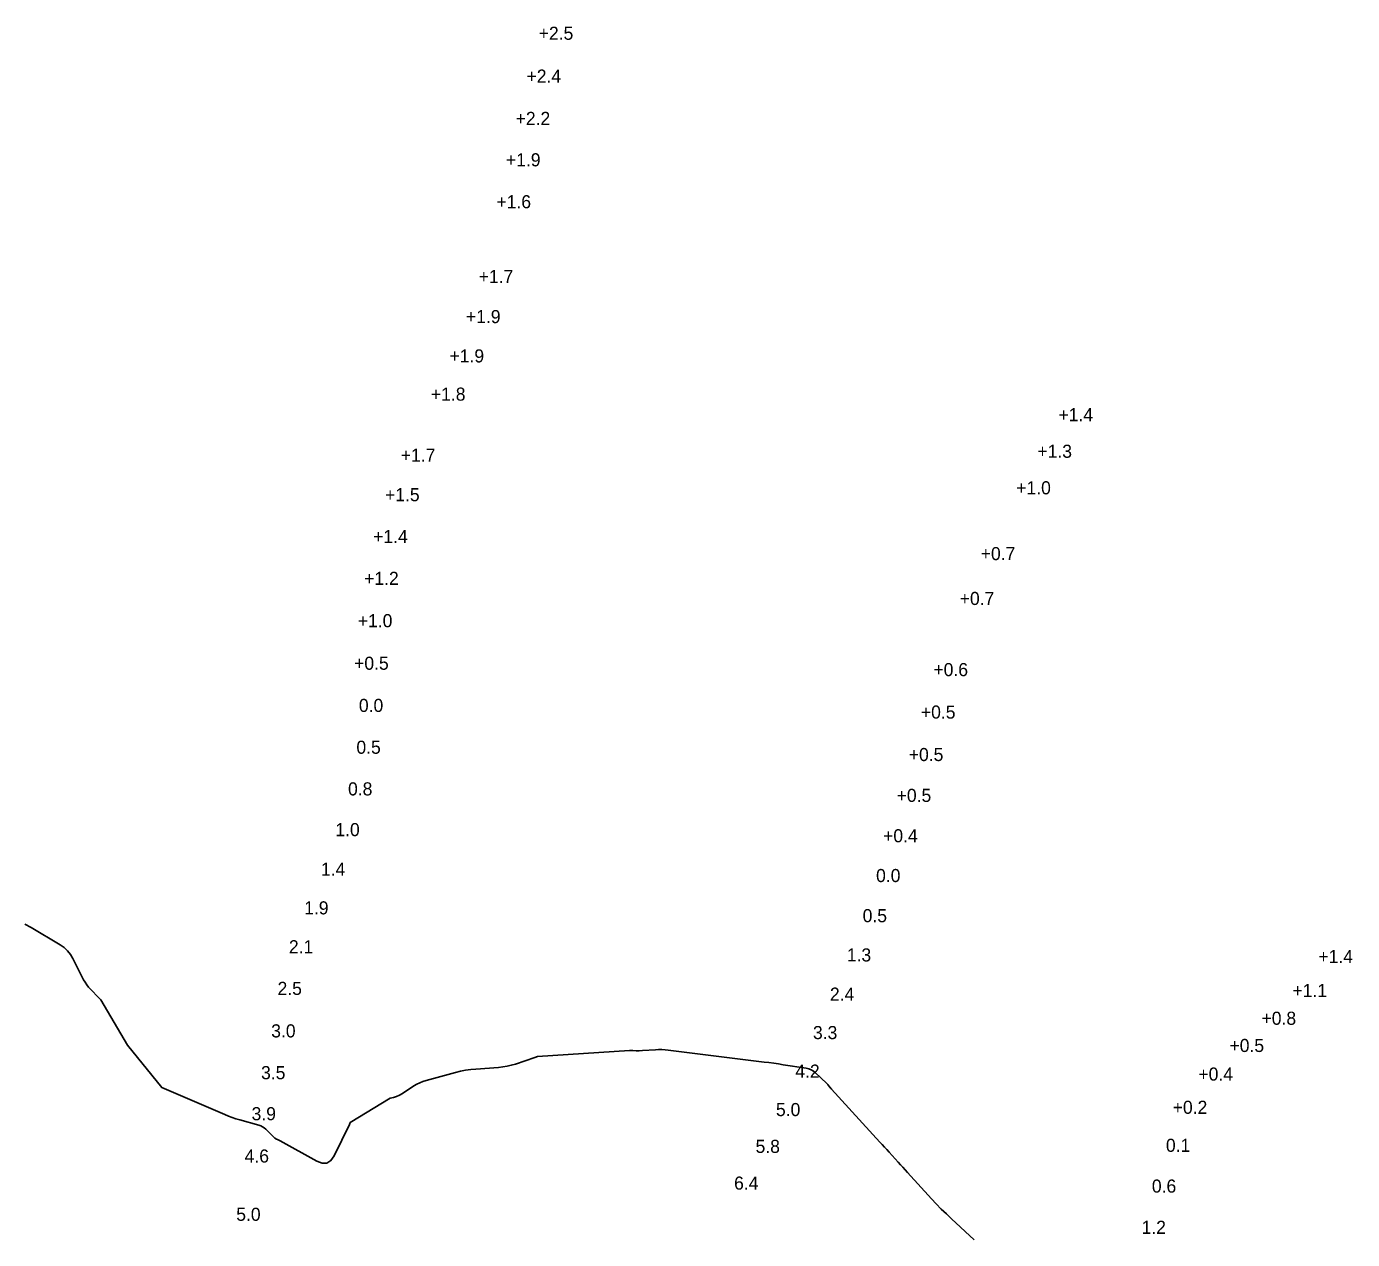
# Model space of a CAD drawing. Extents: x 837127 to 848654, y 3074248 to 3079868.
# Drawn here: x 845153 to 845469.2, y 3079120.3 to 3079409.6 of the extents above; entities that cross this region are included whole.
import ezdxf

# ---------------------------------------------------------------- set-up
doc = ezdxf.new("R2010")
doc.units = 0
for name, color, linetype in [('V-HYDS-MAJR', 7, 'Continuous'), ('V-HYDS-SOUN', 7, 'Continuous'), ('V-HYDS-SOUN-EXSS', 7, 'Continuous')]:
    doc.layers.add(name, color=color, linetype=linetype)

msp = doc.modelspace()

# ---------------------------------------------------------------- linework, layer by layer
at = {"layer": 'V-HYDS-MAJR'}
msp.add_lwpolyline([(845152.6, 3079195.56), (845154.1, 3079194.7), (845161, 3079190.61), (845161.95, 3079189.96), (845162.78, 3079189.19), (845163.49, 3079188.31), (845164.08, 3079187.31), (845166.62, 3079182.28), (845166.97, 3079181.66), (845167.35, 3079181.08), (845167.79, 3079180.52), (845168.27, 3079180), (845170.28, 3079177.99), (845170.7, 3079177.47), (845177.11, 3079166.7), (845185.26, 3079156.57), (845200.28, 3079150.09), (845201.16, 3079149.72), (845202.05, 3079149.39), (845202.95, 3079149.09), (845203.86, 3079148.83), (845208.39, 3079147.58), (845208.87, 3079147.42), (845209.31, 3079147.2), (845209.71, 3079146.92), (845210.09, 3079146.59), (845212.05, 3079144.63), (845212.14, 3079144.54), (845212.25, 3079144.46), (845212.36, 3079144.39), (845212.48, 3079144.33), (845212.97, 3079144.1), (845213.09, 3079144.04), (845213.21, 3079143.99), (845213.33, 3079143.92), (845213.45, 3079143.86), (845222.25, 3079138.98), (845223.53, 3079138.49), (845224.64, 3079138.54), (845225.58, 3079139.13), (845226.36, 3079140.26), (845230.03, 3079147.75), (845230.19, 3079148.21), (845239.72, 3079153.98), (845240.5, 3079154.16), (845241.26, 3079154.42), (845241.98, 3079154.75), (845242.67, 3079155.16), (845245.39, 3079156.94), (845246.08, 3079157.36), (845246.8, 3079157.71), (845247.54, 3079158.01), (845248.31, 3079158.25), (845255.27, 3079160.13), (845256.48, 3079160.42), (845257.7, 3079160.66), (845258.92, 3079160.84), (845260.16, 3079160.96), (845265.55, 3079161.36), (845266.58, 3079161.47), (845267.59, 3079161.64), (845268.6, 3079161.87), (845269.59, 3079162.16), (845274.19, 3079163.69), (845274.83, 3079163.92), (845296.83, 3079165.42), (845297.59, 3079165.36), (845298.36, 3079165.33), (845299.13, 3079165.33), (845299.9, 3079165.36), (845302.97, 3079165.56), (845303.74, 3079165.6), (845304.5, 3079165.59), (845305.27, 3079165.55), (845306.03, 3079165.48), (845328.91, 3079162.63), (845330.04, 3079162.49), (845331.17, 3079162.33), (845332.3, 3079162.17), (845333.42, 3079162), (845338.9, 3079161.15), (845339.52, 3079161.01), (845340.1, 3079160.78), (845340.64, 3079160.46), (845341.13, 3079160.06), (845343.75, 3079157.6), (845343.86, 3079157.49), (845343.97, 3079157.38), (845344.07, 3079157.26), (845344.17, 3079157.15), (845344.56, 3079156.67), (845344.66, 3079156.55), (845344.76, 3079156.43), (845344.86, 3079156.31), (845344.96, 3079156.2), (845356.49, 3079143.55), (845357.04, 3079142.95), (845357.59, 3079142.35), (845358.13, 3079141.74), (845358.68, 3079141.14), (845360.86, 3079138.73), (845361.41, 3079138.13), (845361.95, 3079137.53), (845362.5, 3079136.92), (845363.05, 3079136.32), (845368.81, 3079130.03), (845369.96, 3079128.79), (845371.14, 3079127.58), (845372.35, 3079126.4), (845373.58, 3079125.23), (845378.97, 3079120.24)], dxfattribs=at)

# ---------------------------------------------------------------- texts
at = {"layer": 'V-HYDS-SOUN'}
for s, p in [('+2.5 ', (845275.14, 3079406.46)), ('+2.4 ', (845272.24, 3079396.24)), ('+2.2 ', (845269.64, 3079386.15)), ('+1.9 ', (845267.33, 3079376.28)), ('+1.6 ', (845265.06, 3079366.28)), ('+1.7 ', (845260.83, 3079348.44)), ('+1.9 ', (845257.79, 3079338.88)), ('+1.9 ', (845253.87, 3079329.5)), ('+1.8 ', (845249.43, 3079320.39)), ('+1.4 ', (845399.09, 3079315.49)), ('+1.7 ', (845242.25, 3079305.83)), ('+1.3 ', (845394.06, 3079306.76)), ('+1.5 ', (845238.49, 3079296.4)), ('+1.0 ', (845389.02, 3079298.04)), ('+1.4 ', (845235.67, 3079286.43)), ('+0.7 ', (845380.55, 3079282.35)), ('+1.2 ', (845233.51, 3079276.44)), ('+0.7 ', (845375.54, 3079271.65)), ('+1.0 ', (845232, 3079266.35)), ('+0.5 ', (845231.12, 3079256.2)), ('+0.6 ', (845369.27, 3079254.68)), (' 0.0', (845231.1, 3079246.14)), ('+0.5 ', (845366.28, 3079244.55)), ('0.5', (845231.67, 3079236.16)), ('+0.5 ', (845363.39, 3079234.42)), ('0.8', (845229.67, 3079226.23)), ('+0.5 ', (845360.5, 3079224.68)), ('1.0', (845226.65, 3079216.51)), ('+0.4 ', (845357.27, 3079215.05)), ('1.4', (845223.2, 3079207.07)), (' 0.0', (845354.43, 3079205.56)), ('1.9', (845219.21, 3079197.85)), ('0.5', (845352.39, 3079195.99)), ('2.1', (845215.57, 3079188.57)), ('1.3', (845348.62, 3079186.62)), ('+1.4 ', (845461.07, 3079186.25)), ('2.5', (845212.86, 3079178.64)), ('2.4', (845344.59, 3079177.27)), ('+1.1 ', (845454.88, 3079178.14)), ('+0.8 ', (845447.51, 3079171.52)), ('3.0', (845211.35, 3079168.51)), ('3.3', (845340.54, 3079168.1)), ('+0.5 ', (845439.87, 3079165.03)), ('3.5', (845208.93, 3079158.54)), ('4.2', (845336.33, 3079158.91)), ('3.9', (845206.67, 3079148.75)), ('5.0', (845331.72, 3079149.74)), ('+0.2 ', (845426.33, 3079150.28)), ('4.6', (845205.01, 3079138.66)), ('5.8', (845326.85, 3079140.96)), ('0.1', (845424.71, 3079141.21)), ('6.4', (845321.73, 3079132.2)), ('0.6', (845421.36, 3079131.49)), ('5.0', (845203.01, 3079124.76)), ('1.2', (845418.9, 3079121.65))]:
    msp.add_text(s, height=3.125, dxfattribs=at).set_placement(p)
at = {"layer": 'V-HYDS-SOUN-EXSS'}
msp.add_text('+0.4 ', height=3.125, dxfattribs=at).set_placement((845432.46, 3079158.21))

doc.saveas('drawing.dxf')
